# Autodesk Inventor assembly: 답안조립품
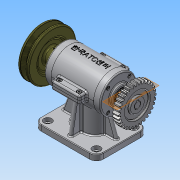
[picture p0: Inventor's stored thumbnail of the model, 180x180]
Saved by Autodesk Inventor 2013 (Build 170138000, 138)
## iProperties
Created: 2015-09
Part Number: 답안조립품
Document SubType Name: Assembly
Designer: Administrator
Author: Administrator
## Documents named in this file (17)
- C:\Users\Administrator\Desktop\350908V1026\답안조립품.iam
- C:\Users\Administrator\Desktop\350908V1026\본체.ipt
- C:\Users\Administrator\Desktop\350908V1026\M3x0.5x8.ipt
- C:\Users\Administrator\Desktop\350908V1026\M4x0.5x14.ipt
- C:\Users\Administrator\Desktop\350908V1026\V-벨트풀리.ipt
- C:\Users\Administrator\Desktop\350908V1026\가변스프링.ipt
- C:\Users\Administrator\Desktop\350908V1026\뒤커버.ipt
- C:\Users\Administrator\Desktop\350908V1026\멈춤나사.ipt
- C:\Users\Administrator\Desktop\350908V1026\베어링 6201.ipt
- C:\Users\Administrator\Desktop\350908V1026\베어링 6202.ipt
- C:\Users\Administrator\Desktop\350908V1026\본체 커버.ipt
- C:\Users\Administrator\Desktop\350908V1026\스퍼기어.ipt
- C:\Users\Administrator\Desktop\350908V1026\슬라이드.ipt
- C:\Users\Administrator\Desktop\350908V1026\앞커버.ipt
- C:\Users\Administrator\Desktop\350908V1026\오일실.ipt
- C:\Users\Administrator\Desktop\350908V1026\키4x4.ipt
- C:\Users\Administrator\Desktop\350908V1026\편심축.ipt
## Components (14 placed, 4 different names)
1. M4x0.5x14:1
2. V-벨트풀리:1
3. 가변스프링:1
4. M4x0.5x14:2
5. M4x0.5x14:3
6. M4x0.5x14:4
7. M3x0.5x8:2
8. M3x0.5x8:3
9. M3x0.5x8:4
10. M3x0.5x8:5
11. M3x0.5x8:1
12. M3x0.5x8:6
13. M3x0.5x8:7
14. M3x0.5x8:8
